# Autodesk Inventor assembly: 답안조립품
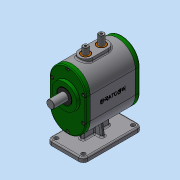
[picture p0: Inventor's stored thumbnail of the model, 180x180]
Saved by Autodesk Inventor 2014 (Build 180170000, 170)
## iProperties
Created: 2018-10
Part Number: 답안조립품
Document SubType Name: Assembly
Designer: kb542
Author: kb542
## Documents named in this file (15)
- C:\Users\kb542\Desktop\381007V1064\답안조립품.iam
- C:\Users\kb542\Desktop\381007V1064\본체.ipt
- C:\Users\kb542\Desktop\381007V1064\가변스프링1.ipt
- C:\Users\kb542\Desktop\381007V1064\가변스프링2.ipt
- C:\Users\kb542\Desktop\381007V1064\뒤커버.ipt
- C:\Users\kb542\Desktop\381007V1064\메인축.ipt
- C:\Users\kb542\Desktop\381007V1064\베어링 608.ipt
- C:\Users\kb542\Desktop\381007V1064\베어링 6003.ipt
- C:\Users\kb542\Desktop\381007V1064\볼트 M4.ipt
- C:\Users\kb542\Desktop\381007V1064\부시.ipt
- C:\Users\kb542\Desktop\381007V1064\서브축.ipt
- C:\Users\kb542\Desktop\381007V1064\슬라이더.ipt
- C:\Users\kb542\Desktop\381007V1064\앞커버.ipt
- C:\Users\kb542\Desktop\381007V1064\오일실 8 22 7.ipt
- C:\Users\kb542\Desktop\381007V1064\오일실 17 32 8.ipt
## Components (2 placed, 2 different names)
1. 가변스프링1:1
2. 가변스프링2:1
